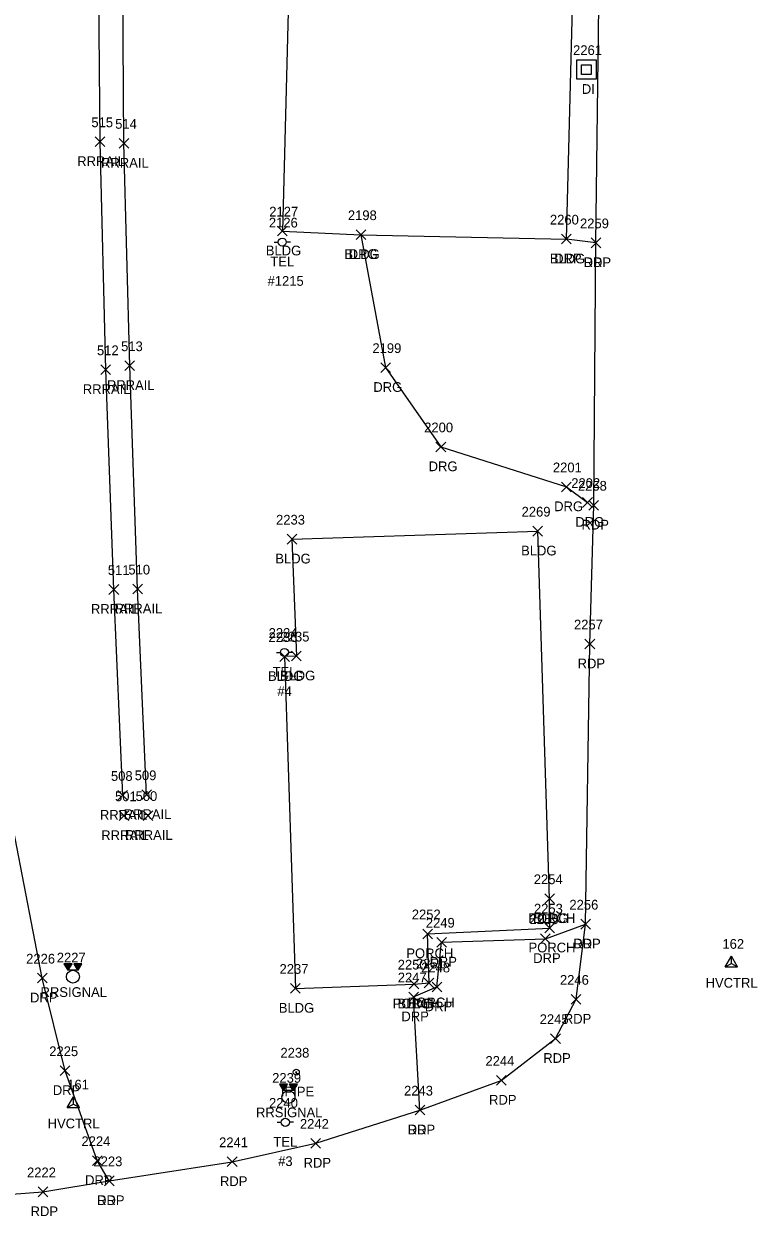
# Model space of a CAD drawing. Extents: x 1767353 to 1772625, y 740790 to 747702.
# Drawn here: x 1770137.8 to 1770288.7, y 741105.6 to 741351 of the extents above; entities that cross this region are included whole.
import ezdxf

# ---------------------------------------------------------------- set-up
doc = ezdxf.new("R2010")
doc.units = 0
for name, color, linetype in [('C_A', 7, 'Continuous'), ('C_I', 7, 'Continuous'), ('CPSM', 7, 'Continuous'), ('D_A', 7, 'Continuous'), ('D_I', 7, 'Continuous'), ('DS', 7, 'Continuous'), ('L_A', 7, 'Continuous'), ('L_I', 7, 'Continuous'), ('L_TIC', 7, 'Continuous'), ('LBC', 7, 'Continuous'), ('LBF', 7, 'Continuous'), ('M_A', 7, 'Continuous'), ('M_I', 7, 'Continuous'), ('MPIP', 7, 'Continuous'), ('P_A', 7, 'Continuous'), ('P_I', 7, 'Continuous'), ('P_TIC', 7, 'Continuous'), ('PET', 7, 'Continuous'), ('R_A', 7, 'Continuous'), ('R_I', 7, 'Continuous'), ('R_TIC', 7, 'Continuous'), ('RDG', 7, 'Continuous'), ('RDP', 7, 'Continuous'), ('RR', 7, 'Continuous'), ('TCSH', 7, 'Continuous'), ('U_A', 7, 'Continuous'), ('U_C', 7, 'Continuous'), ('U_I', 7, 'Continuous'), ('UP', 7, 'Continuous')]:
    doc.layers.add(name, color=color, linetype=linetype)

msp = doc.modelspace()

# ---------------------------------------------------------------- linework, layer by layer
at = {"layer": 'CPSM'}
for p, q in [((1770282.17, 741156.89), (1770283.42, 741159.06)), ((1770282.17, 741156.89), (1770283.42, 741159.06)), ((1770282.17, 741156.89), (1770283.42, 741159.06)), ((1770282.17, 741156.89), (1770283.42, 741157.61)), ((1770282.17, 741156.89), (1770283.42, 741157.61)), ((1770282.17, 741156.89), (1770283.42, 741157.61)), ((1770284.67, 741156.89), (1770283.42, 741159.06)), ((1770283.42, 741157.61), (1770283.42, 741159.06)), ((1770284.67, 741156.89), (1770283.42, 741159.06)), ((1770283.42, 741157.61), (1770283.42, 741159.06)), ((1770284.67, 741156.89), (1770283.42, 741159.06)), ((1770283.42, 741157.61), (1770283.42, 741159.06)), ((1770283.42, 741157.61), (1770283.42, 741157.61)), ((1770283.42, 741157.61), (1770284.67, 741156.89)), ((1770283.42, 741157.61), (1770283.42, 741157.61)), ((1770283.42, 741157.61), (1770284.67, 741156.89)), ((1770283.42, 741157.61), (1770283.42, 741157.61)), ((1770283.42, 741157.61), (1770284.67, 741156.89)), ((1770282.17, 741156.89), (1770284.67, 741156.89)), ((1770282.17, 741156.89), (1770284.67, 741156.89)), ((1770282.17, 741156.89), (1770284.67, 741156.89)), ((1770146.76, 741127.94), (1770148.01, 741130.11)), ((1770146.76, 741127.94), (1770148.01, 741128.66)), ((1770146.76, 741127.94), (1770149.26, 741127.94)), ((1770149.26, 741127.94), (1770148.01, 741130.11)), ((1770148.01, 741128.66), (1770148.01, 741130.11)), ((1770148.01, 741128.66), (1770148.01, 741128.66)), ((1770148.01, 741128.66), (1770149.26, 741127.94))]:
    msp.add_line(p, q, dxfattribs=at)
at = {"layer": 'DS'}
for p, q in [((1770251.59, 741343.55), (1770255.59, 741343.55)), ((1770251.59, 741339.55), (1770251.59, 741343.55)), ((1770252.59, 741340.55), (1770252.59, 741342.55)), ((1770252.59, 741342.55), (1770254.59, 741342.55)), ((1770253.59, 741341.55), (1770253.59, 741341.55)), ((1770253.59, 741341.55), (1770253.59, 741341.55)), ((1770254.59, 741342.55), (1770254.59, 741340.55)), ((1770255.59, 741343.55), (1770255.59, 741339.55)), ((1770255.59, 741339.55), (1770251.59, 741339.55)), ((1770254.59, 741340.55), (1770252.59, 741340.55))]:
    msp.add_line(p, q, dxfattribs=at)
at = {"layer": 'L_TIC'}
for points in [[(1770190.02, 741307.31), (1770192.02, 741309.31)], [(1770192.02, 741307.31), (1770190.02, 741309.31)], [(1770206.19, 741306.57), (1770208.19, 741308.57)], [(1770208.19, 741306.57), (1770206.19, 741308.57)], [(1770248.47, 741305.66), (1770250.47, 741307.66)], [(1770250.47, 741305.66), (1770248.47, 741307.66)], [(1770191.98, 741243.91), (1770193.98, 741245.91)], [(1770193.98, 741243.91), (1770191.98, 741245.91)], [(1770191.98, 741243.91), (1770193.98, 741245.91)], [(1770193.98, 741243.91), (1770191.98, 741245.91)], [(1770242.56, 741245.56), (1770244.56, 741247.56)], [(1770244.56, 741245.56), (1770242.56, 741247.56)], [(1770242.56, 741245.56), (1770244.56, 741247.56)], [(1770244.56, 741245.56), (1770242.56, 741247.56)], [(1770190.48, 741219.74), (1770192.48, 741221.74)], [(1770192.48, 741219.74), (1770190.48, 741221.74)], [(1770192.9, 741219.85), (1770194.9, 741221.85)], [(1770194.9, 741219.85), (1770192.9, 741221.85)], [(1770245.02, 741169.91), (1770247.02, 741171.91)], [(1770247.02, 741169.91), (1770245.02, 741171.91)], [(1770245.02, 741169.91), (1770247.02, 741171.91)], [(1770247.02, 741169.91), (1770245.02, 741171.91)], [(1770245.05, 741163.87), (1770247.05, 741165.87)], [(1770247.05, 741163.87), (1770245.05, 741165.87)], [(1770219.9, 741162.68), (1770221.9, 741164.68)], [(1770221.9, 741162.68), (1770219.9, 741164.68)], [(1770192.7, 741151.46), (1770194.7, 741153.46)], [(1770194.7, 741151.46), (1770192.7, 741153.46)], [(1770217.11, 741152.34), (1770219.11, 741154.34)], [(1770219.11, 741152.34), (1770217.11, 741154.34)], [(1770217.11, 741152.34), (1770219.11, 741154.34)], [(1770219.11, 741152.34), (1770217.11, 741154.34)], [(1770220.2, 741152.57), (1770222.2, 741154.57)], [(1770222.2, 741152.57), (1770220.2, 741154.57)]]:
    msp.add_lwpolyline(points, dxfattribs=at)
at = {"layer": 'LBC'}
for points in [[(1770194.44, 741438.49), (1770191.02, 741308.31), (1770207.19, 741307.57), (1770249.47, 741306.66), (1770252.07, 741407.47), (1770234.09, 741407.87), (1770235.03, 741437.35)], [(1770192.98, 741244.91), (1770243.56, 741246.56)], [(1770246.02, 741170.91), (1770243.56, 741246.56)], [(1770192.98, 741244.91), (1770193.9, 741220.85), (1770191.48, 741220.74), (1770193.7, 741152.46), (1770218.11, 741153.34)]]:
    msp.add_lwpolyline(points, dxfattribs=at)
at = {"layer": 'LBF'}
msp.add_lwpolyline([(1770218.11, 741153.34), (1770221.2, 741153.57), (1770220.9, 741163.68), (1770246.05, 741164.87), (1770246.02, 741170.91)], dxfattribs=at)
at = {"layer": 'MPIP'}
for radius in [0.625, 0.0833]:
    msp.add_circle((1770193.88, 741135.22), radius, dxfattribs=at)
at = {"layer": 'P_TIC'}
for points in [[(1770254.54, 741304.89), (1770256.54, 741306.89)], [(1770256.54, 741304.89), (1770254.54, 741306.89)], [(1770254.1, 741250.89), (1770256.1, 741252.89)], [(1770256.1, 741250.89), (1770254.1, 741252.89)], [(1770253.29, 741222.33), (1770255.29, 741224.33)], [(1770255.29, 741222.33), (1770253.29, 741224.33)], [(1770252.41, 741164.68), (1770254.41, 741166.68)], [(1770254.41, 741164.68), (1770252.41, 741166.68)], [(1770250.45, 741149.21), (1770252.45, 741151.21)], [(1770252.45, 741149.21), (1770250.45, 741151.21)], [(1770246.23, 741141.13), (1770248.23, 741143.13)], [(1770248.23, 741141.13), (1770246.23, 741143.13)], [(1770235.07, 741132.53), (1770237.07, 741134.53)], [(1770237.07, 741132.53), (1770235.07, 741134.53)], [(1770218.32, 741126.41), (1770220.32, 741128.41)], [(1770220.32, 741126.41), (1770218.32, 741128.41)], [(1770196.89, 741119.58), (1770198.89, 741121.58)], [(1770198.89, 741119.58), (1770196.89, 741121.58)], [(1770179.69, 741115.78), (1770181.69, 741117.78)], [(1770181.69, 741115.78), (1770179.69, 741117.78)], [(1770154.4, 741111.86), (1770156.4, 741113.86)], [(1770156.4, 741111.86), (1770154.4, 741113.86)], [(1770140.73, 741109.59), (1770142.73, 741111.59)], [(1770142.73, 741109.59), (1770140.73, 741111.59)]]:
    msp.add_lwpolyline(points, dxfattribs=at)
at = {"layer": 'PET'}
msp.add_lwpolyline([(1770127.99, 741109.54), (1770141.73, 741110.59), (1770155.4, 741112.86), (1770180.69, 741116.78), (1770197.89, 741120.58), (1770219.32, 741127.41), (1770236.07, 741133.53), (1770247.23, 741142.13), (1770251.45, 741150.21), (1770253.41, 741165.68), (1770254.29, 741223.33), (1770255.1, 741251.89), (1770255.54, 741305.89), (1770256.82, 741408.89)], dxfattribs=at)
at = {"layer": 'R_TIC'}
for points in [[(1770152.5, 741325.69), (1770154.5, 741327.69)], [(1770154.5, 741325.69), (1770152.5, 741327.69)], [(1770157.4, 741325.37), (1770159.4, 741327.37)], [(1770159.4, 741325.37), (1770157.4, 741327.37)], [(1770206.19, 741306.57), (1770208.19, 741308.57)], [(1770208.19, 741306.57), (1770206.19, 741308.57)], [(1770248.47, 741305.66), (1770250.47, 741307.66)], [(1770250.47, 741305.66), (1770248.47, 741307.66)], [(1770254.54, 741304.89), (1770256.54, 741306.89)], [(1770256.54, 741304.89), (1770254.54, 741306.89)], [(1770153.66, 741278.77), (1770155.66, 741280.77)], [(1770155.66, 741278.77), (1770153.66, 741280.77)], [(1770158.62, 741279.6), (1770160.62, 741281.6)], [(1770160.62, 741279.6), (1770158.62, 741281.6)], [(1770211.25, 741279.22), (1770213.25, 741281.22)], [(1770213.25, 741279.22), (1770211.25, 741281.22)], [(1770222.63, 741262.9), (1770224.63, 741264.9)], [(1770224.63, 741262.9), (1770222.63, 741264.9)], [(1770248.46, 741254.67), (1770250.46, 741256.67)], [(1770250.46, 741254.67), (1770248.46, 741256.67)], [(1770252.81, 741251.45), (1770254.81, 741253.45)], [(1770254.81, 741251.45), (1770252.81, 741253.45)], [(1770155.33, 741233.55), (1770157.33, 741235.55)], [(1770157.33, 741233.55), (1770155.33, 741235.55)], [(1770160.21, 741233.64), (1770162.21, 741235.64)], [(1770162.21, 741233.64), (1770160.21, 741235.64)], [(1770157.18, 741191.17), (1770159.18, 741193.17)], [(1770159.18, 741191.17), (1770157.18, 741193.17)], [(1770162.08, 741191.31), (1770164.08, 741193.31)], [(1770164.08, 741191.31), (1770162.08, 741193.31)], [(1770157.45, 741186.98), (1770159.45, 741188.98)], [(1770159.45, 741186.98), (1770157.45, 741188.98)], [(1770162.34, 741187.03), (1770164.34, 741189.03)], [(1770164.34, 741187.03), (1770162.34, 741189.03)], [(1770252.41, 741164.68), (1770254.41, 741166.68)], [(1770254.41, 741164.68), (1770252.41, 741166.68)], [(1770222.8, 741160.96), (1770224.8, 741162.96)], [(1770224.8, 741160.96), (1770222.8, 741162.96)], [(1770244.15, 741161.69), (1770246.15, 741163.69)], [(1770246.15, 741161.69), (1770244.15, 741163.69)], [(1770140.6, 741153.57), (1770142.6, 741155.57)], [(1770142.6, 741153.57), (1770140.6, 741155.57)], [(1770221.84, 741151.75), (1770223.84, 741153.75)], [(1770223.84, 741151.75), (1770221.84, 741153.75)], [(1770217.03, 741149.7), (1770219.03, 741151.7)], [(1770219.03, 741149.7), (1770217.03, 741151.7)], [(1770145.3, 741134.52), (1770147.3, 741136.52)], [(1770147.3, 741134.52), (1770145.3, 741136.52)], [(1770218.32, 741126.41), (1770220.32, 741128.41)], [(1770220.32, 741126.41), (1770218.32, 741128.41)], [(1770151.93, 741116.01), (1770153.93, 741118.01)], [(1770153.93, 741116.01), (1770151.93, 741118.01)], [(1770154.4, 741111.86), (1770156.4, 741113.86)], [(1770156.4, 741111.86), (1770154.4, 741113.86)]]:
    msp.add_lwpolyline(points, dxfattribs=at)
at = {"layer": 'RDG'}
msp.add_lwpolyline([(1770207.19, 741307.57), (1770212.25, 741280.22), (1770223.63, 741263.9), (1770249.46, 741255.67), (1770253.81, 741252.45)], dxfattribs=at)
at = {"layer": 'RDP'}
for points in [[(1770255.54, 741305.89), (1770249.47, 741306.66)], [(1770155.4, 741112.86), (1770152.93, 741117.01), (1770146.3, 741135.52), (1770141.6, 741154.57), (1770134.21, 741192.95), (1770128.25, 741218.07), (1770123.64, 741238.95), (1770122.76, 741253.1)], [(1770219.32, 741127.41), (1770218.03, 741150.7), (1770222.84, 741152.75), (1770223.8, 741161.96), (1770245.15, 741162.69), (1770253.41, 741165.68)]]:
    msp.add_lwpolyline(points, dxfattribs=at)
at = {"layer": 'RR'}
for points in [[(1770158.18, 741192.17), (1770156.33, 741234.55), (1770154.66, 741279.77), (1770153.5, 741326.69), (1770153.07, 741379.82), (1770153.42, 741422.94), (1770154.43, 741466.02), (1770156.03, 741508.16), (1770157.87, 741545.07), (1770160.69, 741586.39), (1770163.59, 741622.82), (1770166.84, 741658.9), (1770171.01, 741697.88), (1770175.49, 741734.8), (1770180.59, 741775.05), (1770185.91, 741810.5), (1770192.47, 741851.32), (1770197.89, 741882.78), (1770201.13, 741901.96), (1770208.66, 741941.8), (1770211.54, 741956.24), (1770217.02, 741983.21), (1770222.11, 742006.18)], [(1770163.08, 741192.31), (1770161.21, 741234.64), (1770159.62, 741280.6), (1770158.4, 741326.37), (1770158.03, 741379.87), (1770158.37, 741422.76), (1770159.48, 741466.41), (1770160.97, 741507.07), (1770162.92, 741544.79), (1770165.6, 741585.33), (1770168.59, 741623.26), (1770171.89, 741657.97), (1770175.98, 741697.29), (1770180.38, 741733.87), (1770185.58, 741774.59), (1770190.55, 741808.84), (1770197.31, 741850.84), (1770202.43, 741880.83), (1770205.99, 741900.79), (1770213.55, 741940.61), (1770216.39, 741955.4), (1770221.78, 741982.04), (1770226.9, 742005.14)]]:
    msp.add_lwpolyline(points, dxfattribs=at)
at = {"layer": 'TCSH'}
for p, q in [((1770147.74, 741157.54), (1770146.07, 741157.54)), ((1770146.07, 741157.54), (1770146.84, 741156.21)), ((1770146.97, 741156.21), (1770147.74, 741157.54)), ((1770149.77, 741157.54), (1770148.11, 741157.54)), ((1770148.11, 741157.54), (1770148.88, 741156.21)), ((1770149, 741156.21), (1770149.77, 741157.54)), ((1770149, 741156.21), (1770146.84, 741156.21)), ((1770147.92, 741154.87), (1770147.92, 741154.87)), ((1770192.08, 741132.78), (1770190.42, 741132.78)), ((1770190.42, 741132.78), (1770191.19, 741131.45)), ((1770193.35, 741131.45), (1770191.19, 741131.45)), ((1770191.31, 741131.45), (1770192.08, 741132.78)), ((1770194.12, 741132.78), (1770192.45, 741132.78)), ((1770192.45, 741132.78), (1770193.22, 741131.45)), ((1770193.35, 741131.45), (1770194.12, 741132.78)), ((1770192.27, 741130.11), (1770192.27, 741130.11))]:
    msp.add_line(p, q, dxfattribs=at)
for points in [[(1770146.12, 741157.47), (1770147.69, 741157.47)], [(1770148.13, 741157.49), (1770149.74, 741157.49)], [(1770146.19, 741157.33), (1770147.62, 741157.33)], [(1770146.27, 741157.2), (1770147.54, 741157.2)], [(1770146.35, 741157.07), (1770147.46, 741157.07)], [(1770146.42, 741156.93), (1770147.39, 741156.93)], [(1770146.5, 741156.8), (1770147.31, 741156.8)], [(1770146.58, 741156.67), (1770147.23, 741156.67)], [(1770146.65, 741156.53), (1770147.16, 741156.53)], [(1770146.73, 741156.4), (1770147.08, 741156.4)], [(1770146.81, 741156.27), (1770147, 741156.27)], [(1770148.21, 741157.36), (1770149.67, 741157.36)], [(1770148.29, 741157.23), (1770149.59, 741157.23)], [(1770148.36, 741157.09), (1770149.51, 741157.09)], [(1770148.44, 741156.96), (1770149.44, 741156.96)], [(1770148.52, 741156.83), (1770149.36, 741156.83)], [(1770148.6, 741156.69), (1770149.28, 741156.69)], [(1770148.67, 741156.56), (1770149.21, 741156.56)], [(1770148.75, 741156.43), (1770149.13, 741156.43)], [(1770148.83, 741156.29), (1770149.05, 741156.29)], [(1770190.46, 741132.7), (1770192.04, 741132.7)], [(1770190.54, 741132.57), (1770191.96, 741132.57)], [(1770190.61, 741132.44), (1770191.88, 741132.44)], [(1770190.69, 741132.3), (1770191.81, 741132.3)], [(1770190.77, 741132.17), (1770191.73, 741132.17)], [(1770190.84, 741132.04), (1770191.65, 741132.04)], [(1770190.92, 741131.9), (1770191.58, 741131.9)], [(1770191, 741131.77), (1770191.5, 741131.77)], [(1770191.08, 741131.64), (1770191.42, 741131.64)], [(1770191.15, 741131.5), (1770191.35, 741131.5)], [(1770192.48, 741132.73), (1770194.09, 741132.73)], [(1770192.55, 741132.6), (1770194.01, 741132.6)], [(1770192.63, 741132.47), (1770193.93, 741132.47)], [(1770192.71, 741132.33), (1770193.86, 741132.33)], [(1770192.79, 741132.2), (1770193.78, 741132.2)], [(1770192.86, 741132.07), (1770193.7, 741132.07)], [(1770192.94, 741131.93), (1770193.63, 741131.93)], [(1770193.02, 741131.8), (1770193.55, 741131.8)], [(1770193.09, 741131.67), (1770193.47, 741131.67)], [(1770193.17, 741131.53), (1770193.4, 741131.53)]]:
    msp.add_lwpolyline(points, dxfattribs=at)
for centre in [(1770147.92, 741154.87), (1770192.27, 741130.11)]:
    msp.add_circle(centre, 1.33, dxfattribs=at)
at = {"layer": 'UP'}
for p, q in [((1770189.33, 741306.04), (1770190.16, 741306.04)), ((1770190.99, 741306.05), (1770190.99, 741306.05)), ((1770192.66, 741306.05), (1770191.82, 741306.05)), ((1770191.82, 741306.05), (1770191.82, 741306.05)), ((1770192.66, 741306.05), (1770192.66, 741306.05)), ((1770189.79, 741221.59), (1770190.62, 741221.59)), ((1770191.45, 741221.6), (1770191.45, 741221.6)), ((1770193.12, 741221.6), (1770192.29, 741221.6)), ((1770192.29, 741221.6), (1770192.29, 741221.6)), ((1770193.12, 741221.6), (1770193.12, 741221.6)), ((1770189.96, 741124.9), (1770190.79, 741124.9)), ((1770191.62, 741124.9), (1770191.62, 741124.9)), ((1770193.29, 741124.9), (1770192.45, 741124.9)), ((1770192.45, 741124.9), (1770192.45, 741124.9)), ((1770193.29, 741124.9), (1770193.29, 741124.9))]:
    msp.add_line(p, q, dxfattribs=at)
for centre in [(1770190.99, 741306.05), (1770191.45, 741221.6), (1770191.62, 741124.9)]:
    msp.add_circle(centre, 0.833, dxfattribs=at)

# ---------------------------------------------------------------- texts
at = {"layer": 'C_A'}
for p in [(1770278.12, 741152.61), (1770278.12, 741152.61), (1770278.12, 741152.61), (1770142.71, 741123.66)]:
    msp.add_text('HVCTRL', height=2, dxfattribs=at).set_placement(p)
at = {"layer": 'C_I'}
for s, p in [('162', (1770281.58, 741160.61)), ('162', (1770281.58, 741160.61)), ('162', (1770281.58, 741160.61)), ('161', (1770146.74, 741131.66))]:
    msp.add_text(s, height=2, dxfattribs=at).set_placement(p)
at = {"layer": 'D_A'}
msp.add_text('DI', height=2, dxfattribs=at).set_placement((1770252.65, 741336.55))
at = {"layer": 'D_I'}
msp.add_text('2261', height=2, dxfattribs=at).set_placement((1770250.85, 741344.55))
at = {"layer": 'L_A'}
for s, p in [('BLDG', (1770187.61, 741303.31)), ('BLDG', (1770203.78, 741302.57)), ('BLDG', (1770246.06, 741301.66)), ('BLDG', (1770240.15, 741241.56)), ('BLDG', (1770240.15, 741241.56)), ('BLDG', (1770189.57, 741239.91)), ('BLDG', (1770189.57, 741239.91)), ('BLDG', (1770188.07, 741215.74)), ('BLDG', (1770190.49, 741215.85)), ('PORCH', (1770241.64, 741165.91)), ('BLDG', (1770242.61, 741165.91)), ('PORCH', (1770216.53, 741158.68)), ('PORCH', (1770241.68, 741159.87)), ('PORCH', (1770213.73, 741148.34)), ('BLDG', (1770214.7, 741148.34)), ('PORCH', (1770216.82, 741148.57)), ('BLDG', (1770190.29, 741147.46))]:
    msp.add_text(s, height=2, dxfattribs=at).set_placement(p)
at = {"layer": 'L_I'}
for s, p in [('2127', (1770188.32, 741311.31)), ('2198', (1770204.5, 741310.57)), ('2260', (1770246.08, 741309.66)), ('2269', (1770240.25, 741249.56)), ('2269', (1770240.25, 741249.56)), ('2233', (1770189.72, 741247.91)), ('2233', (1770189.72, 741247.91)), ('2236', (1770188.16, 741223.74)), ('2235', (1770190.64, 741223.85)), ('2254', (1770242.76, 741173.91)), ('2254', (1770242.76, 741173.91)), ('2253', (1770242.79, 741167.87)), ('2252', (1770217.65, 741166.68)), ('2237', (1770190.44, 741155.46)), ('2250', (1770214.76, 741156.34)), ('2250', (1770214.76, 741156.34)), ('2251', (1770218.51, 741156.57))]:
    msp.add_text(s, height=2, dxfattribs=at).set_placement(p)
at = {"layer": 'M_A'}
msp.add_text('IPIPE', height=2, dxfattribs=at).set_placement((1770190.72, 741130.22))
at = {"layer": 'M_I'}
msp.add_text('2238', height=2, dxfattribs=at).set_placement((1770190.62, 741138.22))
at = {"layer": 'P_A'}
for p in [(1770253.02, 741300.89), (1770252.58, 741246.89), (1770251.78, 741218.33), (1770250.89, 741160.68), (1770248.94, 741145.21), (1770244.72, 741137.13), (1770233.56, 741128.53), (1770216.81, 741122.41), (1770195.38, 741115.58), (1770178.18, 741111.78), (1770152.89, 741107.86), (1770139.21, 741105.59)]:
    msp.add_text('RDP', height=2, dxfattribs=at).set_placement(p)
at = {"layer": 'P_I'}
for s, p in [('2259', (1770252.27, 741308.89)), ('2258', (1770251.84, 741254.89)), ('2257', (1770251.03, 741226.33)), ('2256', (1770250.09, 741168.68)), ('2246', (1770248.14, 741153.21)), ('2245', (1770243.97, 741145.13)), ('2244', (1770232.81, 741136.53)), ('2243', (1770216.06, 741130.41)), ('2242', (1770194.63, 741123.58)), ('2241', (1770178, 741119.78)), ('2223', (1770152.14, 741115.86)), ('2222', (1770138.47, 741113.59))]:
    msp.add_text(s, height=2, dxfattribs=at).set_placement(p)
at = {"layer": 'R_A'}
for s, p in [('RRRAIL', (1770148.8, 741321.69)), ('RRRAIL', (1770153.7, 741321.37)), ('DRG', (1770204.68, 741302.57)), ('DRP', (1770246.96, 741301.66)), ('DRP', (1770253.02, 741300.89)), ('RRRAIL', (1770149.95, 741274.77)), ('RRRAIL', (1770154.91, 741275.6)), ('DRG', (1770209.74, 741275.22)), ('DRG', (1770221.12, 741258.9)), ('DRG', (1770246.95, 741250.67)), ('DRG', (1770251.3, 741247.45)), ('RRRAIL', (1770151.62, 741229.55)), ('RRRAIL', (1770156.5, 741229.64)), ('RRRAIL', (1770158.37, 741187.31)), ('RRRAIL', (1770153.47, 741187.17)), ('RRRAIL', (1770153.74, 741182.98)), ('RRRAIL', (1770158.63, 741183.03)), ('DRP', (1770250.89, 741160.68)), ('DRP', (1770221.29, 741156.96)), ('DRP', (1770242.64, 741157.69)), ('RRSIGNAL', (1770141.25, 741150.7)), ('DRP', (1770139.09, 741149.57)), ('DRP', (1770215.52, 741145.7)), ('DRP', (1770220.33, 741147.75)), ('DRP', (1770143.78, 741130.52)), ('RRSIGNAL', (1770185.59, 741125.94)), ('DRP', (1770216.81, 741122.41)), ('DRP', (1770150.42, 741112.01)), ('DRP', (1770152.89, 741107.86))]:
    msp.add_text(s, height=2, dxfattribs=at).set_placement(p)
at = {"layer": 'R_I'}
for s, p in [('515', (1770151.71, 741329.69)), ('514', (1770156.61, 741329.37)), ('2198', (1770204.5, 741310.57)), ('2260', (1770246.08, 741309.66)), ('2259', (1770252.27, 741308.89)), ('513', (1770157.83, 741283.6)), ('2199', (1770209.55, 741283.22)), ('512', (1770152.87, 741282.77)), ('2200', (1770220.2, 741266.9)), ('2201', (1770246.69, 741258.67)), ('2202', (1770250.47, 741255.45)), ('511', (1770155.1, 741237.55)), ('510', (1770159.33, 741237.64)), ('508', (1770155.74, 741195.17)), ('509', (1770160.63, 741195.31)), ('501', (1770156.58, 741190.98)), ('500', (1770160.81, 741191.03)), ('2256', (1770250.09, 741168.68)), ('2255', (1770241.89, 741165.69)), ('2249', (1770220.54, 741164.96)), ('2227', (1770144.59, 741157.8)), ('2226', (1770138.29, 741157.57)), ('2248', (1770219.58, 741155.75)), ('2247', (1770214.77, 741153.7)), ('2225', (1770143.04, 741138.52)), ('2239', (1770188.92, 741133.04)), ('2243', (1770216.06, 741130.41)), ('2224', (1770149.67, 741120.01)), ('2223', (1770152.14, 741115.86))]:
    msp.add_text(s, height=2, dxfattribs=at).set_placement(p)
at = {"layer": 'U_A'}
for p in [(1770188.55, 741301.05), (1770189.01, 741216.6), (1770189.18, 741119.9)]:
    msp.add_text('TEL', height=2, dxfattribs=at).set_placement(p)
at = {"layer": 'U_C'}
for s, p in [('#1215', (1770187.97, 741297.05)), ('#4', (1770189.99, 741212.6)), ('#3', (1770190.15, 741115.9))]:
    msp.add_text(s, height=2, dxfattribs=at).set_placement(p)
at = {"layer": 'U_I'}
for s, p in [('2126', (1770188.24, 741309.05)), ('2234', (1770188.19, 741224.6)), ('2240', (1770188.27, 741127.9))]:
    msp.add_text(s, height=2, dxfattribs=at).set_placement(p)

doc.saveas('drawing.dxf')
